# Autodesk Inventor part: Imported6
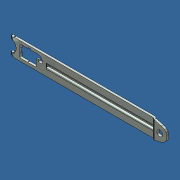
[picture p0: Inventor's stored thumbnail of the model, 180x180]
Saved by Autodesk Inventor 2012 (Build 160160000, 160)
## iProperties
Created: 2016-01
Part Number: Imported6
Material: Steel
Document SubType Name: Modeling
Designer: Admin
Density: 7.85 g/cm^3
Mass: 116.379 g
Surface Area: 119.942 cm^2
Volume: 14.8253 cm^3
Author: Admin
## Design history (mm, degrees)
feature "Base1"
sketch "Sketch1"
  geometry: C1 r 0.46 at (33.548, -10.434); 1 further point
  constraints: 1 centre point
extrude "Extrusion1" join sketch "Sketch1" distance "d0" = 1; taper "d1" = 0 deg
body "Solid1"
